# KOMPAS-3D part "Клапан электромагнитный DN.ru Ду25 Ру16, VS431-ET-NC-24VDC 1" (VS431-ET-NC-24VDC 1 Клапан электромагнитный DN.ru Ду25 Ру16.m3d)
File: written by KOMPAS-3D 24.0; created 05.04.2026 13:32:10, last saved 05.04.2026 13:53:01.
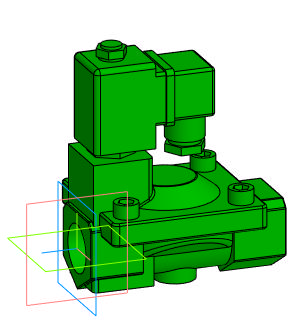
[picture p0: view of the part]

Document properties: Автор: artio; Полное имя файла: C:\Users\artio\OneDrive\Рабочий стол\Клапан электромагнитный DN.ru\VS431\VS431-ET-NC\VS431-ET-NC-24VDC\Ду25\VS431-ET-NC-24VDC 1 Клапан электромагнитный DN.ru Ду25 Ру16.m3d

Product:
- Body: Тело 1  | qty 1
    Масса: 1.729172
- Part/product: Клапан электромагнитный DN.ru Ду25 Ру16  | designation VS431-ET-NC-24VDC 1
    Масса: 1.267
    Раздел спецификации: Прочие изделия
    Примечание: D130-04742
    additional columns: ef56311e-7521-43dc-8291-0e6108b3d81d; artio; c; Шероховатость не задана; Да

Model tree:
1. Операция без истории:1

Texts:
  VS431-ET-NC-24VDC 1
